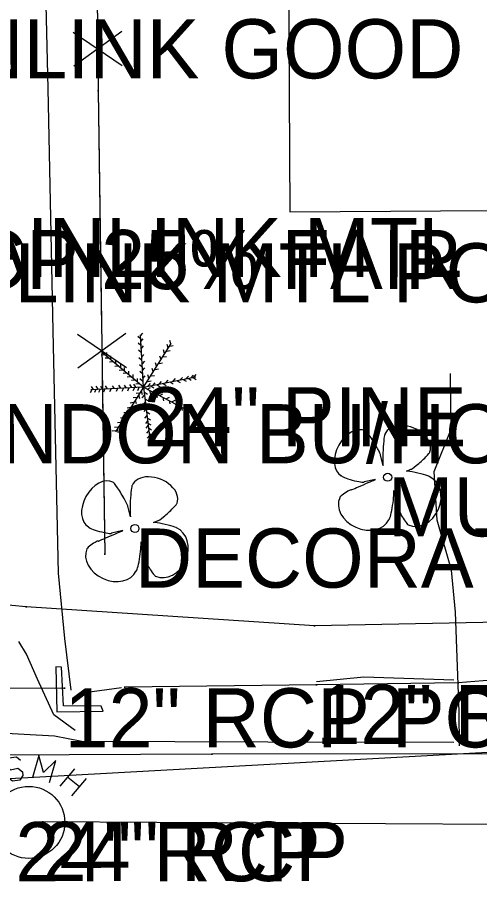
# Model space of a CAD drawing. Extents: x 1304270 to 1306561, y 1876019 to 1876752.
# Drawn here: x 1305346.4 to 1305385.4, y 1876408.6 to 1876482.3 of the extents above; entities that cross this region are included whole.
import ezdxf

# ---------------------------------------------------------------- set-up
doc = ezdxf.new("R2010")
doc.units = 0
for name, color, linetype in [('Default', 7, 'Continuous'), ('S_BUILDING', 7, 'Continuous'), ('S_CROSS_DRAIN', 7, 'Continuous'), ('S_CROSS_DRAIN_ANNOT', 7, 'Continuous'), ('S_DITCHLINE', 7, 'Continuous'), ('S_DRG_PT_SYM', 7, 'Continuous'), ('S_EDGE_PAVEMENT', 7, 'Continuous'), ('S_FENCE', 7, 'Continuous'), ('S_FENCE_ANNOT', 7, 'Continuous'), ('S_FIBER_OPTIC_CABLE', 7, 'Continuous'), ('S_GATE_ANNOT', 7, 'Continuous'), ('S_HEADWALL', 7, 'Continuous'), ('S_MSC_PT_SYM', 7, 'Continuous'), ('S_SANITARY_SEWER', 7, 'Continuous'), ('S_SANITARY_SEWER_ANNOT', 7, 'Continuous'), ('S_SIDE_DRAIN', 7, 'Continuous'), ('S_SIDE_DRAIN_ANNOT', 7, 'Continuous'), ('S_SIDEWALK', 7, 'Continuous'), ('S_SURVEY_TEXT_ANNOT', 7, 'Continuous'), ('S_TREE', 7, 'Continuous'), ('S_TREE_ANNOT', 7, 'Continuous'), ('S_UTL_PT_SYM', 7, 'Continuous'), ('S_WATER_UTILITIES', 7, 'Continuous')]:
    doc.layers.add(name, color=color, linetype=linetype)

msp = doc.modelspace()

# ---------------------------------------------------------------- linework, layer by layer
at = {"layer": 'Default'}
msp.add_line((1304873.941, 1876392.06), (1305473.534, 1876424.943), dxfattribs=at)
at = {"layer": 'S_BUILDING'}
msp.add_lwpolyline([(1305368.981, 1876540.96), (1305369.42, 1876465.829), (1305390.641, 1876465.953), (1305390.622, 1876469.145), (1305406.361, 1876469.237), (1305406.162, 1876503.401), (1305404.582, 1876503.391), (1305404.464, 1876523.501), (1305389.075, 1876523.411), (1305389.062, 1876525.646), (1305391.411, 1876525.659), (1305391.321, 1876541.09)], close=True, dxfattribs=at)
at = {"layer": 'S_CROSS_DRAIN'}
msp.add_line((1305350.386, 1876425.555), (1305326.154, 1876425.439), dxfattribs=at)
at = {"layer": 'S_DITCHLINE'}
for points in [[(1305348.266, 1876506.971), (1305348.616, 1876491.612), (1305348.966, 1876476.252), (1305349.403, 1876455.77), (1305349.841, 1876435.287), (1305350.39, 1876429.748), (1305350.93, 1876425.393)], [(1305371.673, 1876426.112), (1305375.67, 1876426.523), (1305383.261, 1876426.27)], [(1305351.679, 1876425.149), (1305355.188, 1876425.613)]]:
    msp.add_lwpolyline(points, dxfattribs=at)
at = {"layer": 'S_DRG_PT_SYM'}
for points in [[(1305371.658, 1876425.843), (1305371.658, 1876425.893), (1305371.658, 1876425.843), (1305371.608, 1876425.843), (1305371.658, 1876425.843), (1305371.658, 1876425.793), (1305371.658, 1876425.843), (1305371.708, 1876425.843)], [(1305383.624, 1876426.023), (1305383.624, 1876426.073), (1305383.624, 1876426.023), (1305383.574, 1876426.023), (1305383.624, 1876426.023), (1305383.624, 1876425.973), (1305383.624, 1876426.023), (1305383.674, 1876426.023)], [(1305350.386, 1876425.555), (1305350.386, 1876425.605), (1305350.386, 1876425.555), (1305350.336, 1876425.555), (1305350.386, 1876425.555), (1305350.386, 1876425.505), (1305350.386, 1876425.555), (1305350.436, 1876425.555)], [(1305355.495, 1876425.649), (1305355.495, 1876425.699), (1305355.495, 1876425.649), (1305355.445, 1876425.649), (1305355.495, 1876425.649), (1305355.495, 1876425.599), (1305355.495, 1876425.649), (1305355.545, 1876425.649)]]:
    msp.add_lwpolyline(points, dxfattribs=at)
at = {"layer": 'S_EDGE_PAVEMENT'}
for points in [[(1305351.278, 1876421.974), (1305349.475, 1876423.294), (1305348.099, 1876426.311), (1305347.174, 1876428.444), (1305346.543, 1876429.496)], [(1305129.363, 1876422.241), (1305153.047, 1876421.961), (1305176.731, 1876421.682), (1305192.781, 1876421.819), (1305208.83, 1876421.956), (1305222.689, 1876422.089), (1305236.664, 1876421.776), (1305244.109, 1876421.463), (1305257.339, 1876421.298), (1305270.568, 1876421.134), (1305295.068, 1876421.237), (1305319.567, 1876421.34), (1305324.623, 1876421.519), (1305326.394, 1876422.138), (1305337.227, 1876422.202), (1305349.547, 1876421.533), (1305351.837, 1876421.087), (1305367.555, 1876421.039), (1305383.273, 1876420.992)]]:
    msp.add_lwpolyline(points, dxfattribs=at)
at = {"layer": 'S_FENCE'}
for p, q in [((1305352.899, 1876501.588), (1305353.244, 1876476.062)), ((1305351.129, 1876480.997), (1305355.264, 1876478.184)), ((1305351.129, 1876480.997), (1305355.264, 1876478.184)), ((1305355.225, 1876481.052), (1305351.168, 1876478.129)), ((1305355.225, 1876481.052), (1305351.168, 1876478.129)), ((1305353.244, 1876476.062), (1305353.784, 1876436.897)), ((1305351.48, 1876455.471), (1305355.615, 1876452.659)), ((1305351.48, 1876455.471), (1305355.615, 1876452.659)), ((1305355.575, 1876455.527), (1305351.519, 1876452.603)), ((1305355.575, 1876455.527), (1305351.519, 1876452.603))]:
    msp.add_line(p, q, dxfattribs=at)
for points in [[(1305352.899, 1876501.588), (1305353.169, 1876481.59)], [(1305352.899, 1876501.588), (1305353.169, 1876481.59)], [(1305353.223, 1876477.591), (1305353.244, 1876476.062)], [(1305353.223, 1876477.591), (1305353.244, 1876476.062)], [(1305353.244, 1876476.062), (1305353.52, 1876456.065)], [(1305353.244, 1876476.062), (1305353.52, 1876456.065)], [(1305353.575, 1876452.065), (1305353.784, 1876436.897)], [(1305353.575, 1876452.065), (1305353.784, 1876436.897)]]:
    msp.add_lwpolyline(points, dxfattribs=at)
at = {"layer": 'S_FIBER_OPTIC_CABLE'}
for p, q in [((1305347.146, 1876432.44), (1305328.281, 1876434.187)), ((1305371.496, 1876430.825), (1305347.146, 1876432.44)), ((1305399.243, 1876431.395), (1305371.496, 1876430.825))]:
    msp.add_line(p, q, dxfattribs=at)
at = {"layer": 'S_HEADWALL'}
msp.add_lwpolyline([(1305350.142, 1876427.341), (1305349.667, 1876427.367), (1305349.738, 1876423.559), (1305353.65, 1876423.609), (1305353.484, 1876424.045), (1305350.315, 1876424.064)], close=True, dxfattribs=at)
at = {"layer": 'S_MSC_PT_SYM'}
for points in [[(1305353.244, 1876476.062), (1305353.244, 1876476.113), (1305353.244, 1876476.062), (1305353.194, 1876476.062), (1305353.244, 1876476.062), (1305353.244, 1876476.012), (1305353.244, 1876476.062), (1305353.294, 1876476.062)], [(1305353.784, 1876436.897), (1305353.784, 1876436.947), (1305353.784, 1876436.897), (1305353.734, 1876436.897), (1305353.784, 1876436.897), (1305353.784, 1876436.847), (1305353.784, 1876436.897), (1305353.834, 1876436.897)]]:
    msp.add_lwpolyline(points, dxfattribs=at)
at = {"layer": 'S_SANITARY_SEWER'}
for p, q in [((1305350.017, 1876417.277), (1305351.257, 1876418.75)), ((1305350.676, 1876418.052), (1305351.644, 1876417.239)), ((1305352.226, 1876417.936), (1305350.986, 1876416.464)), ((1305626.325, 1876412.772), (1305348.539, 1876414.259))]:
    msp.add_line(p, q, dxfattribs=at)
for points in [[(1305349.126, 1876417.587), (1305349.668, 1876419.447), (1305348.622, 1876418.44), (1305348.234, 1876419.874), (1305347.692, 1876418.014)], [(1305346.684, 1876419.447), (1305346.336, 1876419.719), (1305345.677, 1876419.641), (1305345.444, 1876419.292), (1305345.483, 1876418.982), (1305345.832, 1876418.672), (1305346.452, 1876418.789), (1305346.839, 1876418.479), (1305346.878, 1876418.169), (1305346.607, 1876417.781), (1305345.987, 1876417.704), (1305345.638, 1876417.975)]]:
    msp.add_lwpolyline(points, dxfattribs=at)
msp.add_circle((1305347.369, 1876414.214), 3.048, dxfattribs=at)
at = {"layer": 'S_SIDE_DRAIN'}
for p, q in [((1305371.658, 1876425.843), (1305355.495, 1876425.649)), ((1305383.624, 1876426.023), (1305371.658, 1876425.843)), ((1305387.576, 1876426.332), (1305383.624, 1876426.023))]:
    msp.add_line(p, q, dxfattribs=at)
at = {"layer": 'S_SIDEWALK'}
msp.add_lwpolyline([(1305383.746, 1876420.692), (1305383.726, 1876423.558), (1305383.417, 1876431.978), (1305383.055, 1876435.528), (1305381.852, 1876439.76), (1305381.589, 1876443.862), (1305383.049, 1876447.446), (1305382.988, 1876452.144)], dxfattribs=at)
at = {"layer": 'S_TREE'}
for p, q in [((1305356.808, 1876455.083), (1305356.584, 1876455.282)), ((1305357.063, 1876451.002), (1305356.795, 1876455.438)), ((1305356.805, 1876455.33), (1305356.994, 1876455.563)), ((1305356.841, 1876454.519), (1305356.616, 1876454.718)), ((1305356.834, 1876454.852), (1305357.023, 1876455.086)), ((1305356.867, 1876454.252), (1305357.055, 1876454.486)), ((1305357.063, 1876451.002), (1305359.405, 1876454.686)), ((1305359.134, 1876454.312), (1305359.045, 1876454.599)), ((1305359.27, 1876454.474), (1305359.567, 1876454.518)), ((1305359.379, 1876454.654), (1305359.29, 1876454.941)), ((1305353.779, 1876453.745), (1305353.482, 1876453.704)), ((1305357.063, 1876451.002), (1305353.599, 1876453.912)), ((1305353.637, 1876453.886), (1305353.637, 1876454.186)), ((1305353.954, 1876453.635), (1305353.954, 1876453.935)), ((1305356.87, 1876453.945), (1305356.645, 1876454.143)), ((1305356.905, 1876453.543), (1305357.094, 1876453.776)), ((1305358.837, 1876453.861), (1305358.748, 1876454.147)), ((1305359.025, 1876454.048), (1305359.321, 1876454.092)), ((1305354.128, 1876453.467), (1305353.829, 1876453.443)), ((1305354.489, 1876453.145), (1305354.19, 1876453.12)), ((1305354.308, 1876453.345), (1305354.308, 1876453.645)), ((1305354.721, 1876452.983), (1305354.721, 1876453.283)), ((1305356.896, 1876453.286), (1305356.671, 1876453.485)), ((1305356.97, 1876452.975), (1305357.158, 1876453.208)), ((1305358.167, 1876452.777), (1305358.077, 1876453.063)), ((1305358.379, 1876453.015), (1305358.676, 1876453.059)), ((1305358.541, 1876453.345), (1305358.451, 1876453.631)), ((1305358.702, 1876453.557), (1305358.999, 1876453.601)), ((1305354.947, 1876452.77), (1305354.648, 1876452.746)), ((1305355.308, 1876452.441), (1305355.009, 1876452.417)), ((1305355.134, 1876452.654), (1305355.134, 1876452.954)), ((1305355.457, 1876452.37), (1305355.457, 1876452.67)), ((1305355.825, 1876452.067), (1305355.825, 1876452.367)), ((1305356.934, 1876452.693), (1305356.71, 1876452.892)), ((1305356.973, 1876452.125), (1305356.748, 1876452.324)), ((1305356.983, 1876452.407), (1305357.171, 1876452.641)), ((1305357.87, 1876452.286), (1305357.781, 1876452.573)), ((1305358.031, 1876452.499), (1305358.328, 1876452.543)), ((1305355.644, 1876452.177), (1305355.345, 1876452.153)), ((1305355.986, 1876451.88), (1305355.687, 1876451.856)), ((1305356.354, 1876451.583), (1305356.055, 1876451.559)), ((1305356.192, 1876451.764), (1305356.192, 1876452.064)), ((1305356.547, 1876451.448), (1305356.547, 1876451.748)), ((1305356.986, 1876451.506), (1305356.761, 1876451.705)), ((1305357.008, 1876451.736), (1305357.197, 1876451.97)), ((1305357.063, 1876451.002), (1305361.484, 1876451.869)), ((1305357.412, 1876451.493), (1305357.708, 1876451.537)), ((1305357.508, 1876451.757), (1305357.419, 1876452.044)), ((1305357.696, 1876451.957), (1305357.992, 1876452.001)), ((1305358.937, 1876451.378), (1305359.138, 1876451.6)), ((1305359.569, 1876451.52), (1305359.771, 1876451.742)), ((1305359.902, 1876451.544), (1305360.155, 1876451.384)), ((1305360.162, 1876451.61), (1305360.364, 1876451.832)), ((1305360.412, 1876451.661), (1305360.665, 1876451.5)), ((1305360.646, 1876451.713), (1305360.848, 1876451.935)), ((1305360.838, 1876451.751), (1305361.091, 1876451.59)), ((1305361.091, 1876451.804), (1305361.293, 1876452.026)), ((1305361.244, 1876451.809), (1305361.497, 1876451.648)), ((1305361.317, 1876451.855), (1305361.519, 1876452.077)), ((1305352.695, 1876450.79), (1305352.561, 1876450.521)), ((1305357.063, 1876451.002), (1305352.611, 1876450.791)), ((1305352.844, 1876450.813), (1305352.676, 1876451.062)), ((1305353.044, 1876450.815), (1305352.91, 1876450.547)), ((1305353.231, 1876450.839), (1305353.063, 1876451.087)), ((1305353.386, 1876450.835), (1305353.252, 1876450.566)), ((1305353.631, 1876450.839), (1305353.463, 1876451.087)), ((1305353.805, 1876450.848), (1305353.671, 1876450.579)), ((1305354.031, 1876450.865), (1305353.863, 1876451.113)), ((1305354.315, 1876450.874), (1305354.181, 1876450.605)), ((1305354.599, 1876450.878), (1305354.431, 1876451.126)), ((1305357.063, 1876451.002), (1305354.683, 1876447.228)), ((1305354.876, 1876450.899), (1305354.742, 1876450.631)), ((1305355.154, 1876450.917), (1305354.985, 1876451.165)), ((1305355.36, 1876450.919), (1305355.226, 1876450.65)), ((1305355.631, 1876450.929), (1305355.463, 1876451.178)), ((1305355.831, 1876450.944), (1305355.697, 1876450.676)), ((1305356.07, 1876450.968), (1305355.902, 1876451.216)), ((1305356.289, 1876450.951), (1305356.155, 1876450.683)), ((1305356.406, 1876451.007), (1305356.237, 1876451.255)), ((1305356.715, 1876451.286), (1305356.416, 1876451.262)), ((1305356.676, 1876450.964), (1305356.542, 1876450.696)), ((1305357.063, 1876451.002), (1305360.979, 1876448.957)), ((1305357.063, 1876451.002), (1305357.594, 1876446.63)), ((1305357.392, 1876450.822), (1305357.658, 1876450.962)), ((1305357.44, 1876451.088), (1305357.642, 1876451.31)), ((1305357.683, 1876451.119), (1305357.936, 1876450.958)), ((1305357.84, 1876451.146), (1305358.042, 1876451.368)), ((1305358.199, 1876451.196), (1305358.452, 1876451.036)), ((1305358.369, 1876451.249), (1305358.571, 1876451.471)), ((1305358.715, 1876451.312), (1305358.968, 1876451.152)), ((1305359.321, 1876451.441), (1305359.575, 1876451.281)), ((1305356.496, 1876450.138), (1305356.197, 1876450.104)), ((1305356.734, 1876450.506), (1305356.436, 1876450.472)), ((1305356.644, 1876450.344), (1305356.72, 1876450.054)), ((1305356.857, 1876450.68), (1305356.933, 1876450.39)), ((1305357.125, 1876450.327), (1305356.929, 1876450.099)), ((1305357.141, 1876450.577), (1305357.397, 1876450.421)), ((1305357.573, 1876450.725), (1305357.644, 1876450.434)), ((1305357.87, 1876450.596), (1305358.135, 1876450.736)), ((1305358.154, 1876450.422), (1305358.225, 1876450.13)), ((1305358.425, 1876450.293), (1305358.69, 1876450.433)), ((1305358.689, 1876450.144), (1305358.76, 1876449.853)), ((1305358.979, 1876450.009), (1305359.245, 1876450.149)), ((1305356.218, 1876449.693), (1305355.92, 1876449.659)), ((1305356.108, 1876449.493), (1305356.184, 1876449.203)), ((1305356.366, 1876449.906), (1305356.442, 1876449.615)), ((1305357.189, 1876449.746), (1305356.993, 1876449.519)), ((1305357.179, 1876450.022), (1305357.436, 1876449.866)), ((1305357.263, 1876449.454), (1305357.52, 1876449.298)), ((1305359.212, 1876449.873), (1305359.283, 1876449.582)), ((1305359.463, 1876449.751), (1305359.729, 1876449.891)), ((1305359.747, 1876449.577), (1305359.818, 1876449.285)), ((1305359.999, 1876449.48), (1305360.264, 1876449.62)), ((1305360.263, 1876449.319), (1305360.334, 1876449.027)), ((1305360.547, 1876449.203), (1305360.813, 1876449.342)), ((1305355.702, 1876448.854), (1305355.404, 1876448.82)), ((1305355.566, 1876448.603), (1305355.642, 1876448.312)), ((1305355.966, 1876449.273), (1305355.668, 1876449.24)), ((1305355.85, 1876449.067), (1305355.926, 1876448.777)), ((1305357.273, 1876449.185), (1305357.077, 1876448.957)), ((1305357.344, 1876448.617), (1305357.148, 1876448.39)), ((1305357.328, 1876448.906), (1305357.584, 1876448.75)), ((1305360.754, 1876449.067), (1305360.825, 1876448.776)), ((1305360.941, 1876448.996), (1305361.206, 1876449.136)), ((1305355.166, 1876448.028), (1305354.868, 1876447.995)), ((1305355.405, 1876448.403), (1305355.107, 1876448.369)), ((1305355.321, 1876448.222), (1305355.397, 1876447.932)), ((1305357.409, 1876448.159), (1305357.213, 1876447.932)), ((1305357.399, 1876448.396), (1305357.655, 1876448.24)), ((1305357.431, 1876447.964), (1305357.687, 1876447.808)), ((1305354.715, 1876447.312), (1305354.417, 1876447.278)), ((1305354.915, 1876447.615), (1305354.617, 1876447.582)), ((1305354.837, 1876447.473), (1305354.913, 1876447.183)), ((1305355.063, 1876447.822), (1305355.139, 1876447.532)), ((1305357.447, 1876447.778), (1305357.251, 1876447.551)), ((1305357.506, 1876447.333), (1305357.309, 1876447.106)), ((1305357.476, 1876447.557), (1305357.732, 1876447.401)), ((1305357.541, 1876447.093), (1305357.797, 1876446.937)), ((1305357.551, 1876446.914), (1305357.355, 1876446.686)), ((1305357.579, 1876446.751), (1305357.836, 1876446.595)), ((1305377.309, 1876444.368), (1305377.066, 1876445.261)), ((1305379.257, 1876443.908), (1305379.636, 1876444.071)), ((1305376.66, 1876443.205), (1305375.686, 1876442.988)), ((1305378.195, 1876442.274), (1305378.273, 1876441.835)), ((1305355.966, 1876440.038), (1305355.722, 1876440.931)), ((1305357.914, 1876439.578), (1305358.292, 1876439.74)), ((1305355.316, 1876438.875), (1305354.342, 1876438.658)), ((1305356.851, 1876437.944), (1305356.929, 1876437.505))]:
    msp.add_line(p, q, dxfattribs=at)
for centre in [(1305377.677, 1876443.389), (1305356.333, 1876439.058)]:
    msp.add_circle(centre, 0.341, dxfattribs=at)
for centre, major_axis, ratio, start_param, end_param in [((1305379.338, 1876446.276), (1.894, -0.744), 0.673998, 0, 3.141593), ((1305374.79, 1876445.406), (-1.031, -1.884), 0.662338, 3.141593, 6.283185), ((1305376.443, 1876446.276), (0.622, -1.015), 0.083512, 0, 3.141593), ((1305377.377, 1876445.694), (-0.068, -1.326), 0.068203, 3.141593, 6.283185), ((1305380.434, 1876444.801), (-0.798, -0.73), 0.092159, 0, 3.141593), ((1305357.995, 1876441.945), (1.894, -0.744), 0.673998, 0, 3.141593), ((1305374.722, 1876443.256), (0.964, -0.267), 0.113563, 3.141593, 6.283185), ((1305380.218, 1876443.678), (0.96, -0.23), 0.056001, 0, 3.141593), ((1305380.295, 1876441.402), (0.883, 2.046), 0.81717, 3.141593, 6.283185), ((1305353.446, 1876441.076), (-1.031, -1.884), 0.662338, 3.141593, 6.283185), ((1305355.1, 1876441.945), (0.622, -1.015), 0.083512, 0, 3.141593), ((1305356.033, 1876441.364), (-0.068, -1.326), 0.068203, 3.141593, 6.283185), ((1305375.622, 1876442.762), (1.038, 0.443), 0.002756, 3.141593, 6.283185), ((1305374.107, 1876441.991), (0.477, 0.328), 0.136309, 0, 3.141593), ((1305377.959, 1876441.108), (0.189, 1.312), 0.114148, 3.141593, 5.822668), ((1305375.699, 1876440.729), (2.07, -0.933), 0.760068, 3.141593, 6.283185), ((1305378.527, 1876441.064), (0.254, -0.771), 0.051603, 3.141593, 6.283185), ((1305359.09, 1876440.471), (-0.798, -0.73), 0.092159, 0, 3.141593), ((1305379.102, 1876439.826), (-0.321, 0.467), 0.094289, 0, 3.141593), ((1305353.378, 1876438.925), (0.964, -0.267), 0.113563, 3.141593, 6.283185), ((1305358.874, 1876439.348), (0.96, -0.23), 0.056001, 0, 3.141593), ((1305358.952, 1876437.072), (0.883, 2.046), 0.81717, 3.141593, 6.283185), ((1305354.278, 1876438.432), (1.038, 0.443), 0.002756, 3.141593, 6.283185), ((1305352.763, 1876437.66), (0.477, 0.328), 0.136309, 0, 3.141593), ((1305356.615, 1876436.778), (0.189, 1.312), 0.114148, 3.141593, 5.822668), ((1305354.356, 1876436.399), (2.07, -0.933), 0.760068, 3.141593, 6.283185), ((1305357.183, 1876436.734), (0.254, -0.771), 0.051603, 3.141593, 6.283185), ((1305357.758, 1876435.496), (-0.321, 0.467), 0.094289, 0, 3.141593)]:
    msp.add_ellipse(centre, major_axis=major_axis, ratio=ratio, start_param=start_param, end_param=end_param, dxfattribs=at)
at = {"layer": 'S_UTL_PT_SYM'}
for points in [[(1305347.146, 1876432.44), (1305347.146, 1876432.49), (1305347.146, 1876432.44), (1305347.096, 1876432.44), (1305347.146, 1876432.44), (1305347.146, 1876432.39), (1305347.146, 1876432.44), (1305347.196, 1876432.44)], [(1305371.496, 1876430.825), (1305371.496, 1876430.875), (1305371.496, 1876430.825), (1305371.446, 1876430.825), (1305371.496, 1876430.825), (1305371.496, 1876430.775), (1305371.496, 1876430.825), (1305371.546, 1876430.825)], [(1305362.843, 1876419.995), (1305362.843, 1876420.045), (1305362.843, 1876419.995), (1305362.793, 1876419.995), (1305362.843, 1876419.995), (1305362.843, 1876419.945), (1305362.843, 1876419.995), (1305362.893, 1876419.995)], [(1305347.383, 1876414.046), (1305347.383, 1876414.096), (1305347.383, 1876414.046), (1305347.333, 1876414.046), (1305347.383, 1876414.046), (1305347.383, 1876413.996), (1305347.383, 1876414.046), (1305347.433, 1876414.046)], [(1305348.539, 1876414.259), (1305348.539, 1876414.309), (1305348.539, 1876414.259), (1305348.489, 1876414.259), (1305348.539, 1876414.259), (1305348.539, 1876414.209), (1305348.539, 1876414.259), (1305348.589, 1876414.259)]]:
    msp.add_lwpolyline(points, dxfattribs=at)
at = {"layer": 'S_WATER_UTILITIES'}
for p, q in [((1305362.843, 1876419.995), (1305316.936, 1876419.741)), ((1305400.373, 1876420.004), (1305362.843, 1876419.995))]:
    msp.add_line(p, q, dxfattribs=at)

# ---------------------------------------------------------------- texts
at = {"layer": 'S_CROSS_DRAIN_ANNOT'}
msp.add_text('12" RCP POOR 85% FILL 24.23', height=5, dxfattribs=at).set_placement((1305350.386, 1876420.555))
at = {"layer": 'S_FENCE_ANNOT'}
for s, p in [("4' CHAINLINK GOOD", (1305319.262, 1876477.101)), ("5' CHAINLINK MTL POST", (1305318.506, 1876458.169))]:
    msp.add_text(s, height=5, dxfattribs=at).set_placement(p)
at = {"layer": 'S_GATE_ANNOT'}
msp.add_text("5' 3' CHAINLINK MTL GT POOR", height=5, dxfattribs=at).set_placement((1305319.368, 1876460.305))
at = {"layer": 'S_SANITARY_SEWER_ANNOT'}
for p in [(1305346.234, 1876409.239), (1305348.539, 1876409.259)]:
    msp.add_text('24" RCP', height=5, dxfattribs=at).set_placement(p)
at = {"layer": 'S_SIDE_DRAIN_ANNOT'}
for s, p in [('12" RCP 25% FAIR DEL ABOVE SHOTS 4.21', (1305325.836, 1876459.292)), ('12" RCP 85% FAIR 16.17', (1305371.658, 1876420.843))]:
    msp.add_text(s, height=5, dxfattribs=at).set_placement(p)
at = {"layer": 'S_SURVEY_TEXT_ANNOT'}
msp.add_text('1 STRY WOOD ABANDON BU/HOME', height=5, dxfattribs=at).set_placement((1305282.963, 1876444.567))
at = {"layer": 'S_TREE_ANNOT'}
for s, p in [('24" PINE', (1305357.063, 1876446.002)), ('MULTI BASED SR', (1305377.677, 1876438.389)), ('DECORATIVE BUSH', (1305356.333, 1876434.058))]:
    msp.add_text(s, height=5, dxfattribs=at).set_placement(p)

doc.saveas('drawing.dxf')
